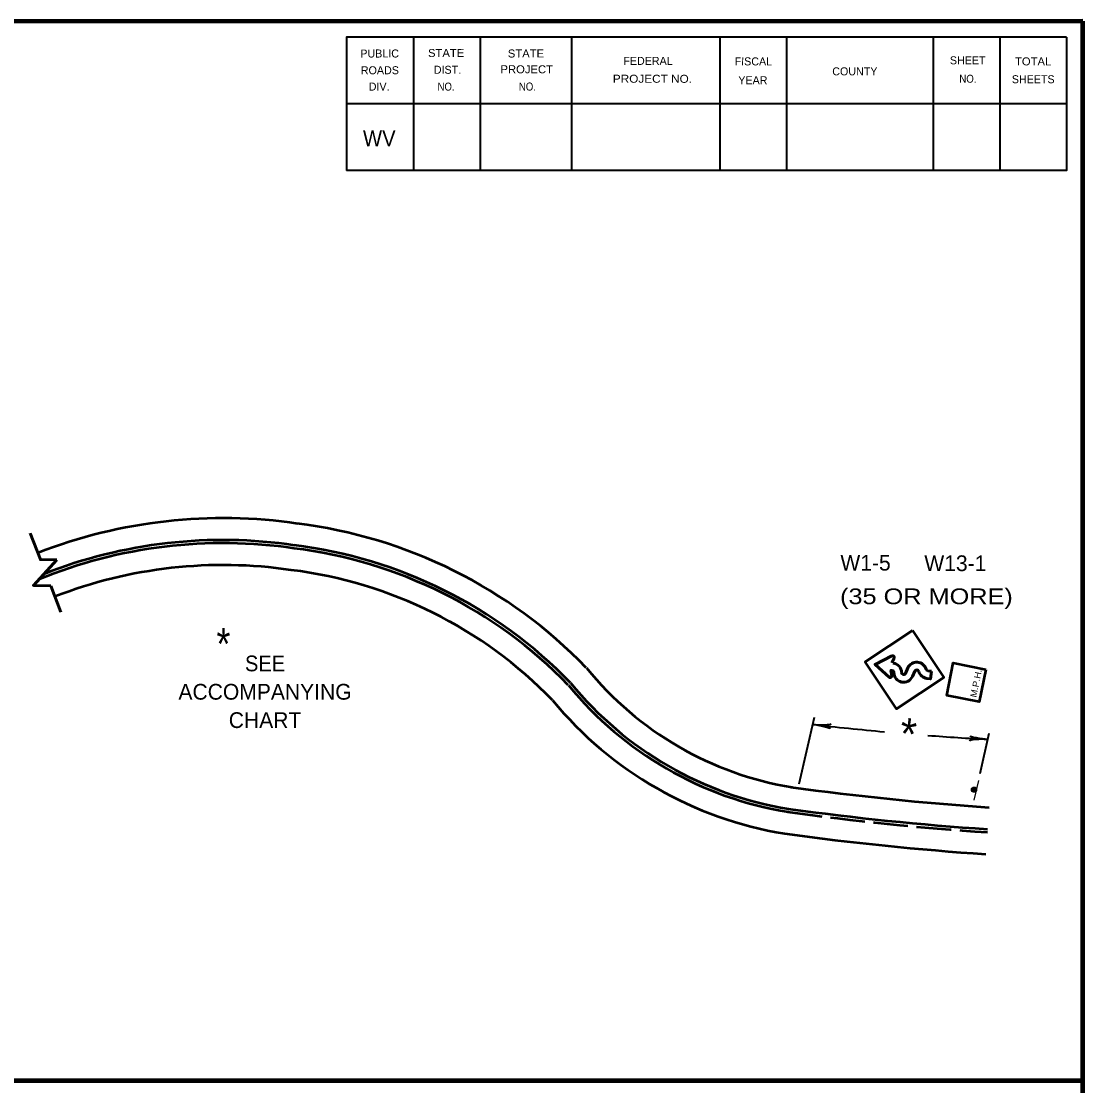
# Model space of a CAD drawing. Extents: x 522 to 1378, y -343 to 201.
# Drawn here: x 1168.8 to 1371, y -8.5 to 194.3 of the extents above; entities that cross this region are included whole.
import ezdxf
from ezdxf.enums import TextEntityAlignment as Align

# ---------------------------------------------------------------- set-up
doc = ezdxf.new("R2010")
doc.units = 0
doc.header["$LTSCALE"] = 1.1
doc.linetypes.add('LONG_DASHED', pattern=[7.5, 6, -1.5])
for name, color, linetype, lineweight in [('1', 7, 'Continuous', 53), ('4', 7, 'Continuous', 25), ('61', 7, 'Continuous', 35)]:
    doc.layers.add(name, color=color, linetype=linetype, lineweight=lineweight)

msp = doc.modelspace()

# ---------------------------------------------------------------- hatches: boundary and pattern name
at = {"layer": '4'}
msp.add_hatch(color=256, dxfattribs=at).paths.add_polyline_path([(1350.398, 48.381, 1), (1350.173, 47.423, 1)])

# ---------------------------------------------------------------- linework, layer by layer
at = {"layer": '1', "lineweight": 158}
msp.add_line((1370.988, -331.84), (1370.988, 194.26), dxfattribs=at)
at = {"layer": '1', "lineweight": 13}
msp.add_line((1370.988, -331.84), (1370.988, 194.26), dxfattribs=at)
at = {"layer": '1', "lineweight": 60}
for p, q in [((1174.422, 86.692), (1176.366, 81.687)), ((1335.075, 72.945), (1334.657, 72.034)), ((1337.238, 70.046), (1337.693, 71.083)), ((1339.021, 70.477), (1338.558, 69.452)), ((1341.479, 70.532), (1342.162, 70.439))]:
    msp.add_line(p, q, dxfattribs=at)
at = {"layer": '1', "lineweight": 35}
for p, q in [((1316.979, 49.029), (1319.885, 61.727)), ((1351.427, 51.004), (1353.177, 58.652))]:
    msp.add_line(p, q, dxfattribs=at)
at = {"layer": '1', "lineweight": 158}
msp.add_lwpolyline([(1370.988, 194.26), (579.288, 194.16), (579.388, -331.84)], dxfattribs=at)
at = {"layer": '1', "lineweight": 60}
for points in [[(1170.524, 96.726), (1172.468, 91.721), (1175.603, 91.703)], [(1175.603, 91.703), (1171.119, 86.788), (1174.422, 86.692)], [(1334.093, 69.319), (1331.442, 71.749), (1334.65, 73.376)], [(1334.698, 70.566), (1334.46, 70.599), (1334.617, 69.609)], [(1342.162, 70.439), (1341.965, 69.004), (1341.28, 69.098)]]:
    msp.add_lwpolyline(points, dxfattribs=at)
at = {"layer": '1'}
for points in [[(1338.537, 78.241), (1344.528, 69.255), (1335.541, 63.265), (1329.551, 72.251)], [(1352.505, 70.79), (1351.27, 64.612), (1345.092, 65.848), (1346.328, 72.025)]]:
    msp.add_lwpolyline(points, close=True, dxfattribs=at)
for centre, radius, start, end in [((1207.247, 2.261), 97.35, 81.57252, 111.22948), ((1210.026, 6.878), 92.402, 44.05398, 82.99476), ((1207.247, 2.261), 93.18, 81.57252, 111.49773), ((1207.247, 2.261), 92.584, 81.57252, 112.25946), ((1210.026, 6.878), 87.637, 44.05398, 82.99476), ((1210.026, 6.878), 88.232, 44.05398, 82.99476), ((1207.247, 2.261), 88.415, 81.57252, 111.22948), ((1210.026, 6.878), 83.467, 44.05398, 82.99476), ((1325.886, 111.039), 63.517, 218.95034, 260.71258), ((1325.886, 111.039), 68.283, 219.26451, 260.71258), ((1325.886, 111.039), 67.687, 219.22241, 260.71258), ((1325.886, 111.039), 72.452, 219.5398, 260.71258), ((1389.575, 586.781), 543.477, 262.15692, 266.15711), ((1389.575, 586.781), 547.646, 262.15692, 266.15711), ((1389.575, 586.781), 552.411, 262.15692, 266.15711)]:
    msp.add_arc(centre, radius, start, end, dxfattribs=at)
at = {"layer": '1', "lineweight": 60}
for centre, radius, start, end in [((1334.782, 73.08), 0.32, 335.46736, 114.08493), ((1334.643, 70.18), 1.843, 0.82547, 82.39269), ((1339.381, 70.328), 1.845, 15.78444, 155.97323), ((1334.299, 69.562), 0.32, 230.27808, 8.89564), ((1334.643, 70.18), 0.389, 0.07689, 82.26795), ((1336.877, 70.199), 1.845, 180.583, 335.9508), ((1336.879, 70.208), 0.393, 180.2747, 335.73877), ((1339.381, 70.318), 0.391, 15.66843, 155.68386), ((1341.531, 70.922), 1.842, 195.67996, 262.18302), ((1341.541, 70.929), 0.396, 194.43789, 260.90807)]:
    msp.add_arc(centre, radius, start, end, dxfattribs=at)
at = {"layer": '1', "lineweight": 35}
for start, end in [(263.33801, 264.78601), (265.66259, 266.86654)]:
    msp.add_arc((1382.617, 600.146), 543.477, start, end, dxfattribs=at)
at = {"layer": '1', "linetype": 'LONG_DASHED'}
msp.add_arc((1389.575, 586.781), 548.242, 262.15692, 266.15711, dxfattribs=at)
at = {"layer": '1', "lineweight": 40}
for centre, major_axis, ratio, start_param, end_param in [((1320.873, 59.931), (-2.069, 0.454), 0.07063, 3.1407148, 5.41811), ((1320.906, 60.517), (-2.15, 0.062), 0.122415, 0.8963533, 3.1415927), ((1351.584, 57.223), (2.15, 0.07), 0.122415, 0.8963533, 3.1415927), ((1351.581, 57.809), (2.093, -0.326), 0.07063, 3.1407148, 5.41811)]:
    msp.add_ellipse(centre, major_axis=major_axis, ratio=ratio, start_param=start_param, end_param=end_param, dxfattribs=at)
at = {"layer": '4'}
msp.add_line((1350.315, 45.923), (1351.192, 49.662), dxfattribs=at)
msp.add_circle((1350.286, 47.902), 0.492, dxfattribs=at)
at = {"layer": '61'}
for p, q in [((1243.488, 191.26), (1243.488, 165.86)), ((1256.188, 191.26), (1256.188, 165.86)), ((1273.588, 191.26), (1273.588, 165.86)), ((1301.888, 191.26), (1301.888, 165.86)), ((1314.588, 191.26), (1314.588, 165.86)), ((1342.488, 191.26), (1342.488, 165.86)), ((1355.188, 191.26), (1355.188, 165.86)), ((1367.888, 178.56), (1230.788, 178.56))]:
    msp.add_line(p, q, dxfattribs=at)
at = {"layer": '61', "lineweight": 158}
msp.add_line((1370.988, -7.57), (579.326, -7.57), dxfattribs=at)
at = {"layer": '61'}
for points in [[(1367.888, 191.26), (1230.788, 191.26), (1230.788, 165.86)], [(1367.888, 191.26), (1367.888, 165.86), (1230.788, 165.86)]]:
    msp.add_lwpolyline(points, dxfattribs=at)

# ---------------------------------------------------------------- texts
at = {"layer": '1'}
for s, height, width, p in [('WV', 3.048, 0.95, (1233.888, 170.46)), ('*', 6, 0.85, (1205.997, 72.675))]:
    msp.add_text(s, height=height, dxfattribs=dict(at, width=width)).set_placement(p)
for s, p in [('W1-5', (1329.624, 89.623)), ('W13-1', (1346.731, 89.523)), ('ACCOMPANYING', (1215.239, 65.041)), ('CHART', (1215.239, 59.641))]:
    msp.add_text(s, height=3, dxfattribs=at).set_placement(p, align=Align.CENTER)
for s, width, p in [('(35 OR MORE)', 1.2, (1341.22, 83.226)), ('SEE', 0.95, (1215.239, 70.441))]:
    msp.add_text(s, height=3, dxfattribs=dict(at, width=width)).set_placement(p, align=Align.CENTER)
at = {"layer": '1', "width": 1.1}
msp.add_text('M.P.H.', height=1.2, rotation=78.499, dxfattribs=at).set_placement((1350.721, 65.396))
at = {"layer": '1'}
msp.add_text('*', height=6, rotation=355.102, dxfattribs=at).set_placement((1335.96, 55.665))
at = {"layer": '61'}
for s, height, rotation, p in [('PUBLIC', 1.525, 0.033, (1233.388, 187.36)), ('FEDERAL', 1.523, 0.007, (1283.488, 185.96)), ('FISCAL', 1.525, 359.942, (1304.688, 185.86)), ('SHEET', 1.525, 0.059, (1345.688, 186.06)), ('ROADS', 1.525, 0.124, (1233.488, 184.16)), ('DIST.', 1.525, 0.056, (1247.388, 184.26)), ('COUNTY', 1.523, 0.069, (1323.288, 183.96)), ('DIV.', 1.525, 359.932, (1234.988, 181.06)), ('YEAR', 1.523, 0.105, (1305.388, 182.26)), ('SHEETS', 1.523, 359.959, (1357.488, 182.46))]:
    msp.add_text(s, height=height, rotation=rotation, dxfattribs=at).set_placement(p)
for s, rotation, width, p in [('STATE', 0.059, 1.05, (1246.288, 187.46)), ('STATE', 0.059, 1.05, (1261.488, 187.36)), ('TOTAL', 359.926, 1.05, (1358.088, 185.86)), ('PROJECT', 359.908, 1.05, (1260.088, 184.36)), ('NO.', 359.852, 0.9, (1248.088, 181.06)), ('NO.', 0.225, 0.9, (1263.588, 181.06)), ('PROJECT NO.', 359.922, 1.1, (1281.488, 182.56)), ('NO.', 359.852, 0.9, (1347.488, 182.56))]:
    msp.add_text(s, height=1.525, rotation=rotation, dxfattribs=dict(at, width=width)).set_placement(p)

doc.saveas('drawing.dxf')
